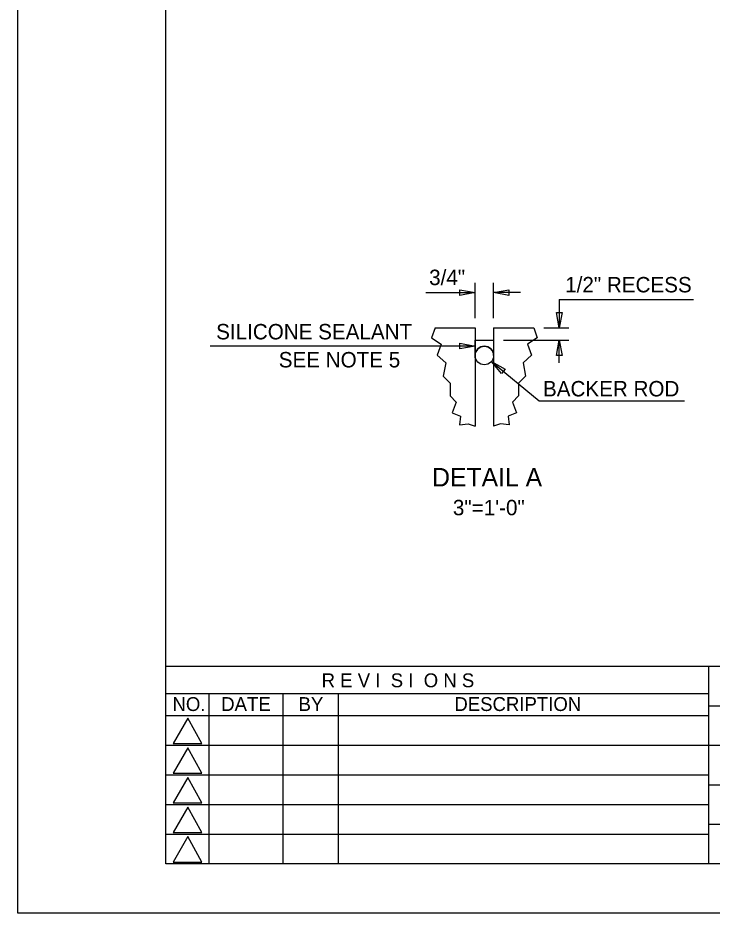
# Model space of a CAD drawing. Extents: x 0 to 68, y 0 to 47.1.
# Drawn here: x 0 to 14.07, y 0 to 18.13 of the extents above; entities that cross this region are included whole.
import ezdxf

# ---------------------------------------------------------------- set-up
doc = ezdxf.new("R2010")
doc.units = 0
for name, color, linetype in [('BORDER_ANNO_Cutsheet', 7, 'Continuous'), ('BRDG_ANNO_Anno-Sheet', 7, 'Continuous'), ('BRDG_ANNO_General-Notes', 7, 'Continuous'), ('BRDG_BASE_Active-Point', 7, 'Continuous'), ('BRDG_BASE_Obj-Line', 7, 'Continuous'), ('BRDG_BASE_Phtline', 7, 'Continuous'), ('BRDG_BASE_Rebar', 7, 'Continuous')]:
    doc.layers.add(name, color=color, linetype=linetype)

msp = doc.modelspace()

# ---------------------------------------------------------------- linework, layer by layer
at = {"layer": 'BORDER_ANNO_Cutsheet'}
msp.add_lwpolyline([(0, 44), (68, 44), (68, 0), (0, 0)], close=True, dxfattribs=at)
at = {"layer": 'BRDG_ANNO_Anno-Sheet'}
for p, q in [((3, 5), (38.5, 5)), ((14, 1), (14, 5)), ((3, 4.45), (14, 4.45)), ((3.875, 1), (3.875, 4.45)), ((5.375, 1), (5.375, 4.45)), ((6.5, 1), (6.5, 4.439)), ((14, 4.2), (19, 4.2)), ((2.995, 4), (14, 4)), ((2.995, 3.4), (14, 3.4)), ((14, 3.4), (19, 3.4)), ((2.995, 2.8), (14, 2.8)), ((14, 2.6), (19, 2.6)), ((2.995, 2.2), (14, 2.2)), ((14, 1.8), (19, 1.8)), ((2.995, 1.6), (14, 1.6))]:
    msp.add_line(p, q, dxfattribs=at)
msp.add_lwpolyline([(3, 43), (67, 43), (67, 1), (3, 1)], close=True, dxfattribs=at)
for points in [[(3.445, 3.949), (3.149, 3.435), (3.729, 3.435), (3.445, 3.949)], [(3.445, 3.349), (3.149, 2.835), (3.729, 2.835), (3.445, 3.349)], [(3.445, 2.749), (3.149, 2.235), (3.729, 2.235), (3.445, 2.749)], [(3.445, 2.149), (3.149, 1.635), (3.729, 1.635), (3.445, 2.149)], [(3.445, 1.549), (3.149, 1.035), (3.729, 1.035), (3.445, 1.549)]]:
    msp.add_lwpolyline(points, dxfattribs=at)
at = {"layer": 'BRDG_ANNO_General-Notes'}
for p, q in [((9.266, 12.054), (9.266, 12.767)), ((9.641, 12.054), (9.641, 12.767)), ((8.266, 12.57), (9.266, 12.57)), ((8.956, 12.512), (8.956, 12.628)), ((8.956, 12.628), (9.266, 12.57)), ((9.266, 12.57), (8.956, 12.512)), ((9.641, 12.57), (9.951, 12.628)), ((10.187, 12.57), (9.641, 12.57)), ((9.951, 12.512), (9.641, 12.57)), ((9.951, 12.628), (9.951, 12.512)), ((10.971, 12.427), (10.971, 11.857)), ((10.971, 12.427), (13.691, 12.427)), ((10.913, 12.167), (11.029, 12.167)), ((10.971, 11.857), (10.913, 12.167)), ((11.029, 12.167), (10.971, 11.857)), ((10.658, 11.857), (11.168, 11.857)), ((9.838, 11.607), (11.168, 11.607)), ((10.913, 11.297), (10.971, 11.607)), ((10.971, 11.148), (10.971, 11.607)), ((10.971, 11.607), (11.029, 11.297)), ((9.266, 11.488), (3.894, 11.488)), ((8.956, 11.43), (8.956, 11.546)), ((8.956, 11.546), (9.266, 11.488)), ((9.266, 11.488), (8.956, 11.43)), ((11.029, 11.297), (10.913, 11.297)), ((9.598, 11.175), (10.561, 10.376)), ((9.799, 10.933), (9.598, 11.175)), ((9.598, 11.175), (9.873, 11.022)), ((9.873, 11.022), (9.799, 10.933)), ((10.561, 10.376), (13.508, 10.376))]:
    msp.add_line(p, q, dxfattribs=at)
at = {"layer": 'BRDG_BASE_Active-Point'}
msp.add_line((0, 0), (0, 0), dxfattribs=at)
at = {"layer": 'BRDG_BASE_Obj-Line'}
for p, q in [((8.453, 11.857), (9.266, 11.857)), ((9.266, 11.857), (9.266, 9.863)), ((9.641, 11.857), (9.641, 9.863)), ((9.641, 11.857), (10.453, 11.857))]:
    msp.add_line(p, q, dxfattribs=at)
for points in [[(8.453, 11.857), (8.384, 11.657), (8.576, 11.525), (8.496, 11.302), (8.669, 11.15), (8.617, 10.875), (8.759, 10.734), (8.759, 10.482), (8.882, 10.35), (8.8, 10.137), (8.972, 10.065), (8.952, 9.893), (9.124, 9.914), (9.266, 9.863)], [(10.453, 11.857), (10.523, 11.657), (10.33, 11.525), (10.41, 11.302), (10.238, 11.15), (10.289, 10.875), (10.148, 10.734), (10.148, 10.482), (10.025, 10.35), (10.107, 10.137), (9.935, 10.065), (9.955, 9.893), (9.783, 9.914), (9.641, 9.863)]]:
    msp.add_lwpolyline(points, dxfattribs=at)
at = {"layer": 'BRDG_BASE_Phtline'}
for p, q in [((9.266, 11.295), (9.266, 11.607)), ((9.266, 11.607), (9.641, 11.607)), ((9.641, 11.607), (9.641, 11.295))]:
    msp.add_line(p, q, dxfattribs=at)
msp.add_arc((9.453, 11.295), 0.188, 0, 180, dxfattribs=at)
at = {"layer": 'BRDG_BASE_Rebar'}
msp.add_circle((9.453, 11.295), 0.188, dxfattribs=at)

# ---------------------------------------------------------------- texts
at = {"layer": 'BRDG_ANNO_Anno-Sheet'}
for s, height, p in [('R E V I  S I  O N S', 0.28125, (6.155, 4.575)), ('NO.', 0.2812, (3.133, 4.094)), ('DATE', 0.2812, (4.12, 4.094)), ('BY', 0.2812, (5.688, 4.094)), ('DESCRIPTION', 0.28125, (8.845, 4.094))]:
    msp.add_text(s, height=height, dxfattribs=at).set_placement(p)
at = {"layer": 'BRDG_ANNO_General-Notes'}
for s, height, p in [('3/4"', 0.3125, (8.334, 12.722)), ('1/2" RECESS', 0.3125, (11.091, 12.574)), ('SILICONE SEALANT', 0.3125, (4.018, 11.622)), ('SEE NOTE 5', 0.3125, (5.286, 11.054)), ('BACKER ROD', 0.3125, (10.641, 10.467)), ('DETAIL A', 0.375, (8.394, 8.642)), ('3"=1\'-0"', 0.3125, (8.815, 8.059))]:
    msp.add_text(s, height=height, dxfattribs=at).set_placement(p)

doc.saveas('drawing.dxf')
